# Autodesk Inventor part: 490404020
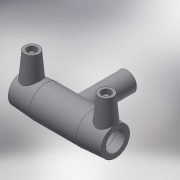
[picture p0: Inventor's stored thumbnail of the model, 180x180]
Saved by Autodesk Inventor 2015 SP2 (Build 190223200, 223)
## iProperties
Created: 2017-06
Part Number: 490404020
Material: Generic
Description: PLASSON TEE 20-20-20
Document SubType Name: Modeling
Designer: KIM
Mass: 57.3761 g
Surface Area: 241.06 cm^2
Volume: 57.3761 cm^3
Density: 1 g/cm^3
Appearance: Default
Author: KIM
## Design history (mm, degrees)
derived "490404.ipt"
feature "Solid1::490404.ipt"
tag "TaggingFeature1"
body "Solid1"
other parameters: "d0" = 96, "d2" = 33, "d3" = 37, "d4" = 24, "d5" = 29.7, "d6" = 19, "d8" = 168 deg, "d10" = 14.8, "d11" = 4.93333, "d13" = 96, "d14" = 17.6296, "d17" = 18, "d19" = 3.52592, "d20" = 168 deg, "d22" = 30.69, "d23" = 33, "d24" = 29.7693, "d25" = 135 deg, "d26" = 67.2, "d27" = 135 deg, "d29" = 39, "d30" = 15, "d31" = 38.4, "d34" = 5 deg, "d35" = 15, "d39" = 5 deg, "d40" = 9.6, "d41" = 4.8, "d42" = 6, "d43" = 0, "d45" = 4, "d46" = 14, "d47" = 0, "d51" = 0, "d52" = 16, "d54" = 0, "d55" = 29.7, "d56" = 33, "d57" = 33.6, "d58" = 135 deg, "d59" = 37, "d60" = 37, "d61" = 135 deg, "d72" = 43.68, "d73" = 21.84, "d75" = 21, "d77" = 0, "d78" = 16, "d80" = 0, "d82" = 43.5, "d83" = 0, "d84" = 3, "d85" = 0, "d86" = 3, "d87" = 0, "d88" = 10.73, "d89" = 2.6825, "d90" = 10.73, "L_" = 96, "L_1" = 37, "D_" = 33, "A_" = 39, "d_2" = 12
